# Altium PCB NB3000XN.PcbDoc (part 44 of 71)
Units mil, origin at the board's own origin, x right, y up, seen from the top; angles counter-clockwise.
Board outline 9527.56 x 6929.77 mil, 6 copper layers (Top Layer, GND+SHIELD, MidLayer1, MidLayer2, P2 - 3V3+5V0, Bottom Layer), stack 62.375 mil thick; 832 components, 1027 nets, 4655 pads, 4981 vias.
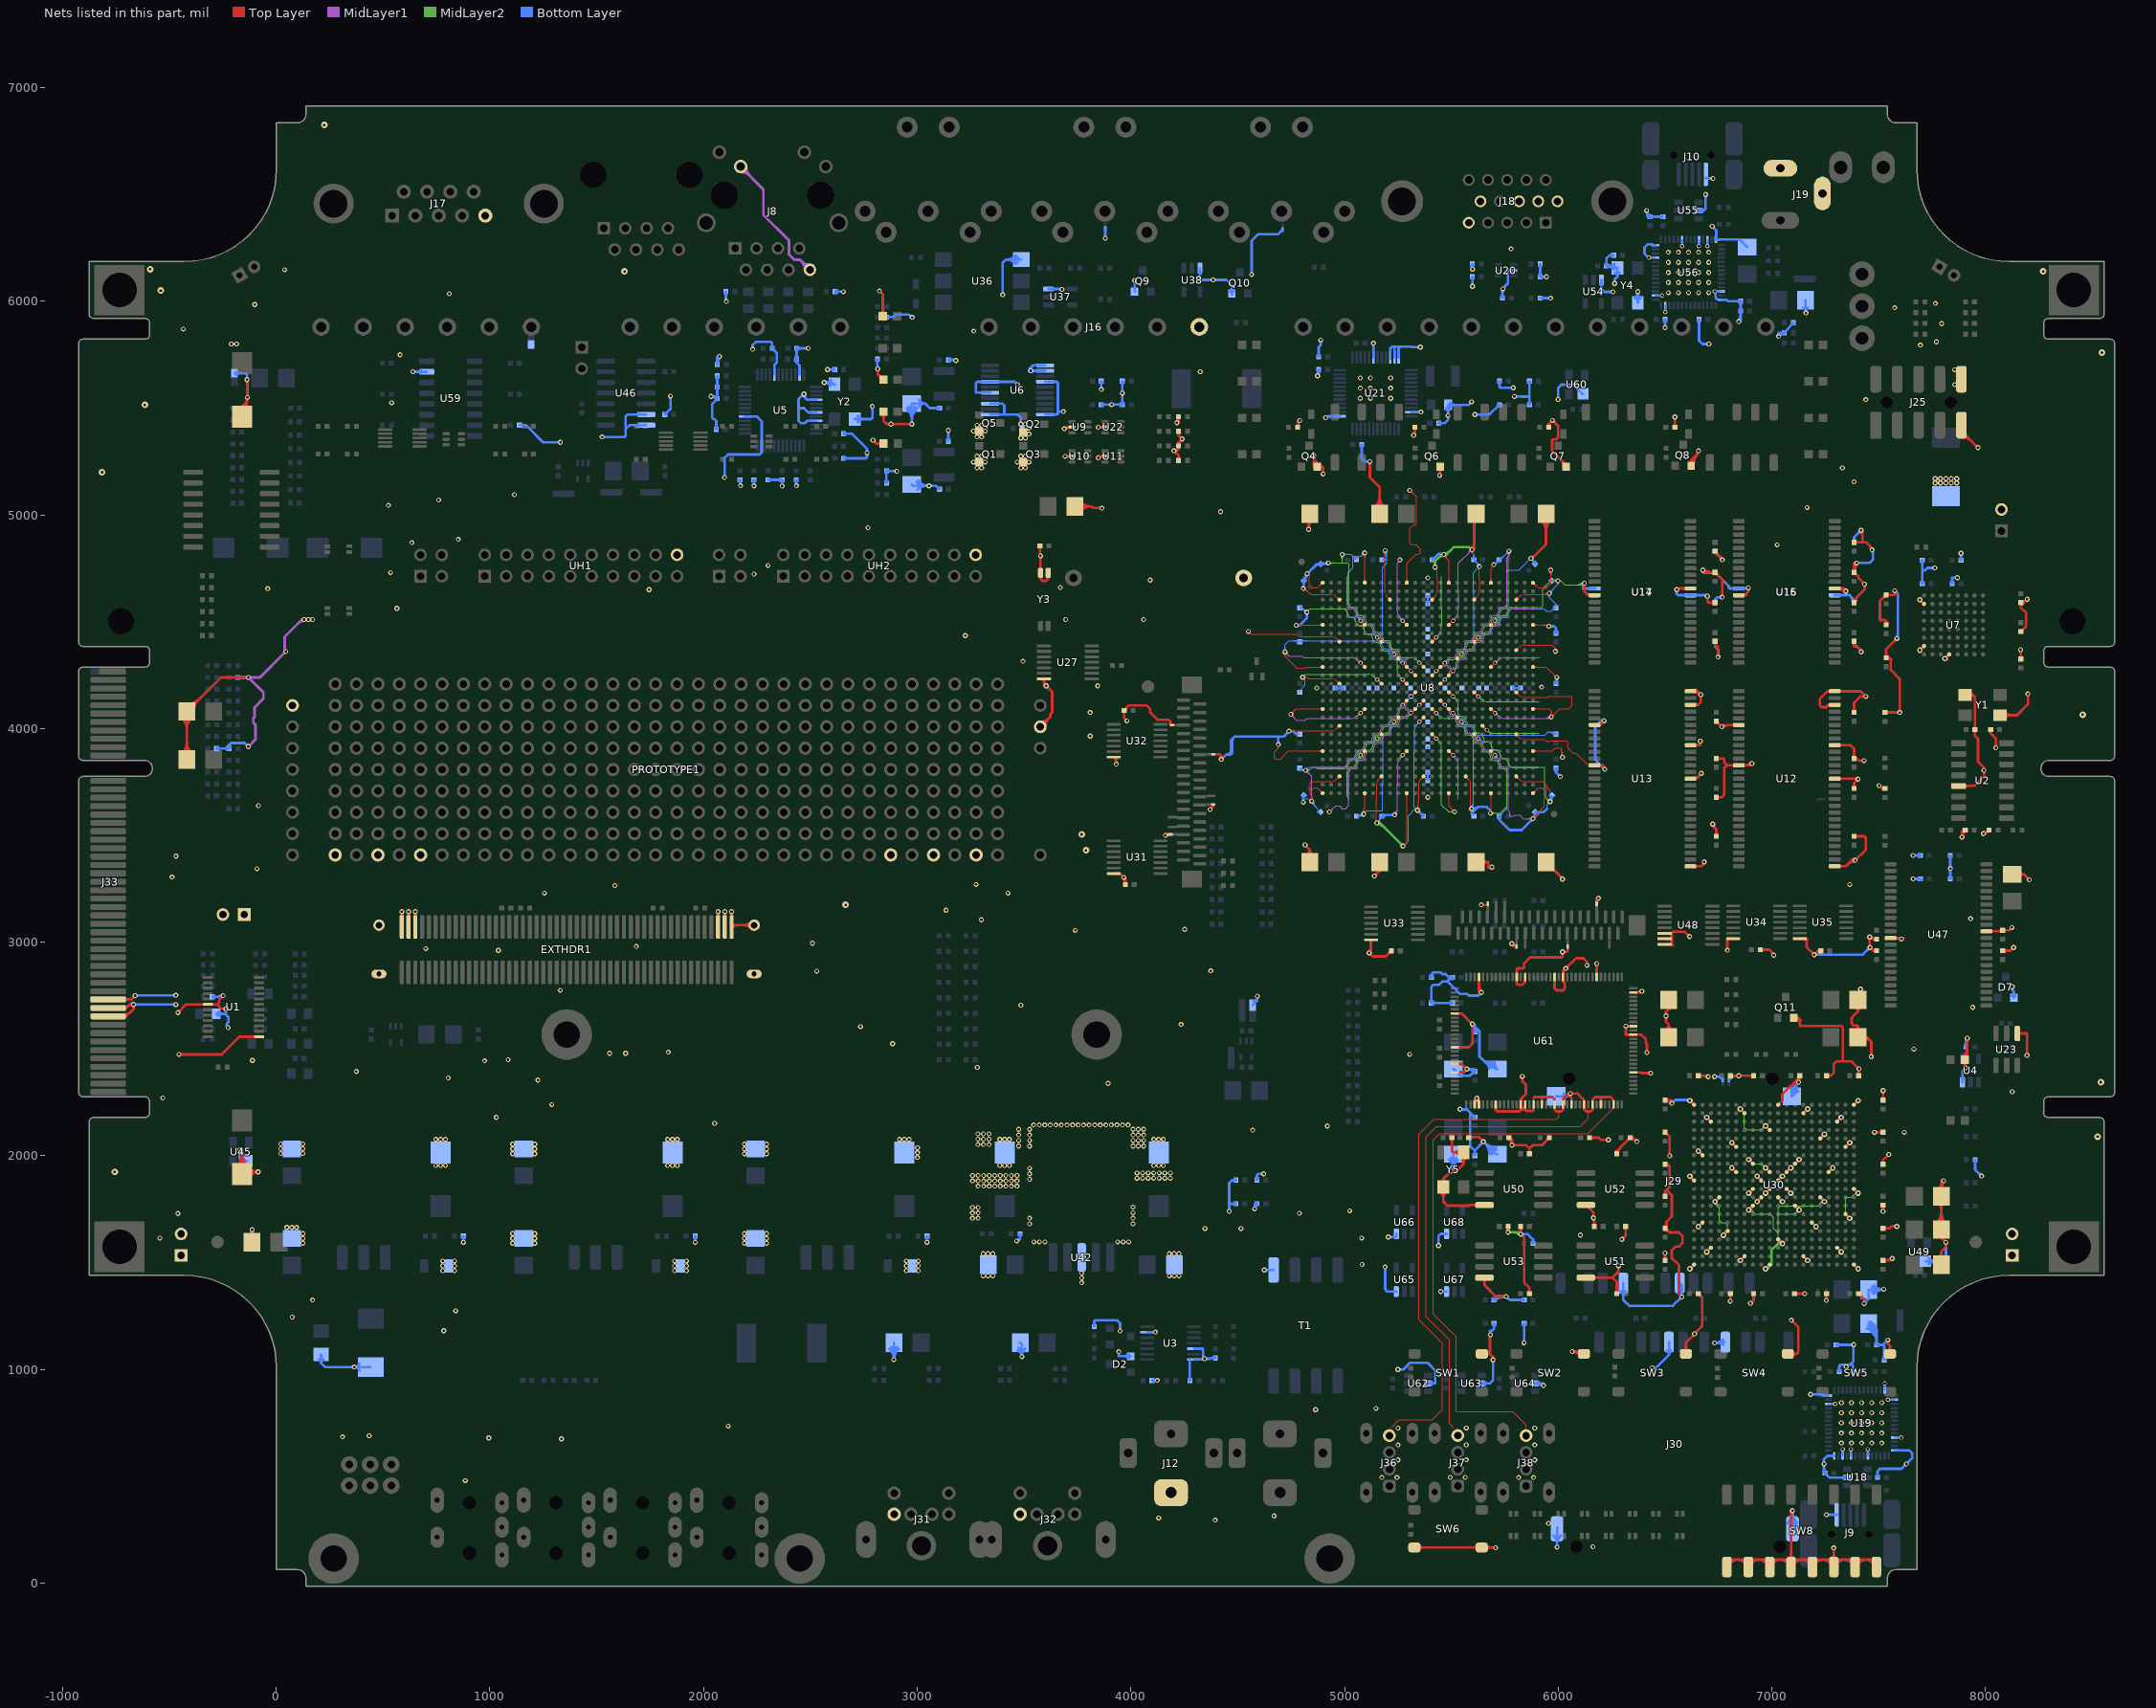
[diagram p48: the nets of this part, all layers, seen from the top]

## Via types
v1: diameter 23, hole 11.81, Top Layer to Bottom Layer, 3672 vias
v2: diameter 26, hole 11.81, Top Layer to Bottom Layer, 461 vias
v3: diameter 19, hole 11.81, Top Layer to Bottom Layer, tented both sides, 396 vias
v4: diameter 23.62, hole 11.81, Top Layer to Bottom Layer, 288 vias
v5: diameter 20, hole 11.81, Top Layer to Bottom Layer, 91 vias
v6: diameter 23, hole 11.81, Top Layer to Bottom Layer, tented both sides, 50 vias
v7: diameter 31, hole 11.81, Top Layer to Bottom Layer, 15 vias
v8: diameter 27.56, hole 11.81, Top Layer to Bottom Layer, tented both sides, 4 vias
v9: diameter 29, hole 11.81, Top Layer to Bottom Layer, 3 vias
v10: diameter 21, hole 11.81, Top Layer to Bottom Layer, 1 vias

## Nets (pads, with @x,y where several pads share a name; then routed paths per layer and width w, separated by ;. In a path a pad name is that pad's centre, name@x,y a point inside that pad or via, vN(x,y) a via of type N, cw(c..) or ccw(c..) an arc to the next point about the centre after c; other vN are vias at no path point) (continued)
GND: (continued)
  Bottom Layer w4: v1@4714.47,4365.09 ccw(c4698.26,4381.31) 4721.19,4381.31 ccw(c4744.13,4381.31) v1@4727.91,4365.09 ; v1@4717.3,4362.26 ccw(c4707.91,4371.65) 4721.19,4371.65 ccw(c4734.47,4371.65) v1@4725.08,4362.26 ; v1(4721.19,4358.37) 4721.19,4391.95 4739.86,4410.62 C320.2@4790,4410.62 ; 4754.08,4410.62 cw(c4754.08,4369.63) C320.2@4783.06,4398.61 ; 4763.73,4410.62 cw(c4763.73,4379.28) C320.2@4785.89,4401.44 ; 4765.19,3982.78 4765.19,3983.04 ; 4773.39,4410.62 cw(c4773.39,4388.94) C320.2@4788.72,4404.27 ; C320.2@4778.55,4410.62 ccw(c4778.55,4417) C320.2@4783.06,4412.49 ; C323.2@4781.37,3969.77 ccw(c4773.52,3965.52) 4773.52,3974.45 ; C323.2@4781.37,3979.12 cw(c4773.52,3983.38) 4773.52,3974.45 ; C322.2@4787.93,3814.28 ccw(c4800.95,3818.83) C322.2@4800.95,3805.04 ; C322.2@4790,3815 C322.2@4799.96,3805.04 ; C323.2@4790,3974.45 4773.52,3974.45 ; C335.2@4790,4169.33 4790,4178.56 4815.19,4203.75 4815.19,4229.04 v1(4803.86,4240.37) ; C320.2@4790,4405.55 4795.07,4410.62 4860,4410.62 4870,4410.62 4938.04,4410.62 5153.78,4410.62 cw(c5153.78,4386.85) 5177.55,4386.85 ccw(c5193.15,4386.85) 5193.15,4371.25 cw(c5193.15,4347.48) 5216.92,4347.48 ; C304.2@4790,4559.19 cw(c4790,4513.22) v1@4822.51,4545.72 ; C304.2@4790,4563.19 cw(c4790,4526.87) v1@4815.68,4552.55 ; C304.2@4790,4565 4803.23,4565 v1(4823.52,4544.71) 4838.75,4559.93 4855.26,4559.93 4860,4559.93 4870,4559.93 4879.78,4559.93 4938.04,4559.93 4996.3,4559.93 cw(c4996.3,4544.33) 5011.9,4544.33 ccw(c5035.67,4544.33) 5035.67,4520.56 cw(c5035.67,4504.96) 5051.27,4504.96 ccw(c5075.04,4504.96) 5075.04,4481.19 cw(c5075.04,4465.59) 5090.64,4465.59 ccw(c5114.41,4465.59) 5114.41,4441.82 5122.53,4441.82 ; C304.2@4790,4567.19 cw(c4790,4540.53) 4808.85,4559.38 ; C304.2@4790,4571.19 cw(c4790,4554.19) 4802.02,4566.21 ; C320.2@4791.28,4404.27 cw(c4806.61,4388.94) 4806.61,4410.62 ; C322.2@4791.71,3815.6 ccw(c4806.58,3820.8) v1@4806.58,3805.04 ; C320.2@4794.11,4401.44 cw(c4816.27,4379.28) 4816.27,4410.62 ; C322.2@4795.49,3816.92 ccw(c4812.22,3822.77) v1@4812.22,3805.04 ; C320.2@4796.94,4398.61 cw(c4825.92,4369.63) 4825.92,4410.62 ; C320.2@4796.94,4412.49 ccw(c4801.45,4417) C320.2@4801.45,4410.62 ; C322.2@4799.26,3818.24 ccw(c4817.86,3824.74) v1(4817.86,3805.04) ; v1@4800.28,4661.72 ccw(c4777.82,4684.18) C310.2@4809.59,4684.18 ; C310.2@4802.65,4684.73 cw(c4785.9,4667.98) 4809.59,4667.98 cw(c4833.27,4667.99) C310.2@4816.53,4684.73 ; v1@4803.11,4658.89 ccw(c4787.47,4674.53) 4809.59,4674.53 ; C310.2@4805.48,4687.56 cw(c4795.56,4677.64) 4809.59,4677.64 cw(c4823.62,4677.64) C310.2@4813.7,4687.56 ; C327.2@4809.59,3688.33 4809.59,3672.04 4834.19,3672.04 v1(4846.19,3660.04) 4846.19,3651.71 4875.19,3622.71 4875.19,3609.59 C326.2@4888.33,3609.59 ; v1@4809.59,4659.98 C310.2@4809.59,4691.67 ; 4809.59,4671.69 ccw(c4823.69,4671.69) v1@4813.72,4661.72 ; v1@4809.99,3799.72 ccw(c4799.96,3792.93) C322.2@4799.96,3805.04 ; v1@4809.99,3810.36 cw(c4799.96,3817.15) C322.2@4799.96,3805.04 ; v1@4814.02,4544.71 ccw(c4791.09,4544.71) 4807.31,4560.93 ccw(c4823.52,4577.14) v1@4823.52,4554.21 ; v1@4817.52,4717.37 v1(4825.19,4725.04) ; v1@4817.86,3813.37 v1(4817.86,3805.04) ; v1@4818.02,4544.71 ccw(c4804.75,4544.71) 4814.14,4554.1 ccw(c4823.52,4563.49) v1@4823.52,4550.21 ; v1@4825.92,3800.02 cw(c4834.97,3794.38) 4834.97,3805.04 ; v1@4825.92,3810.07 ccw(c4834.97,3815.71) 4834.97,3805.04 ; v1@4847.69,3660.04 ccw(c4871.43,3660.04) 4854.64,3643.25 ; v1@4851.69,3660.04 ccw(c4885.09,3660.04) 4861.47,3636.43 ; v1@4855.69,3660.04 ccw(c4898.74,3660.04) 4868.3,3629.6 ; v1(4988.86,4815.04) 5031.3,4815.04 5040.19,4806.15 ; v1@4992.75,4811.15 cw(c5002.14,4801.76) 5002.14,4815.04 cw(c5002.14,4828.32) v1@4992.75,4818.93 ; v1@4995.57,4808.32 cw(c5011.79,4792.11) 5011.79,4815.04 cw(c5011.79,4837.98) v1@4995.57,4821.76 ; 5020.07,3670 5020.07,3679.78 5020.07,3738.04 5020.07,3796.3 cw(c5035.67,3796.3) 5035.67,3811.9 ccw(c5035.67,3835.67) 5059.44,3835.67 5059.44,3843.79 ; 5020.07,4700.22 5020.07,4670 ; 5020.07,4724.74 5020.07,4732.25 ; C308.2@5046.53,4790.26 ccw(c5024.87,4790.82) 5040.19,4806.15 ; C308.2@5050.53,4790.15 ccw(c5037.7,4790.49) 5046.77,4799.56 ccw(c5055.85,4808.64) C308.2@5056.19,4795.81 ; C308.2@5056.08,4799.81 cw(c5055.51,4821.47) 5040.19,4806.15 ; C308.2@5056.34,4790 5040.19,4806.15 ; 5059.44,4536.21 5059.44,4544.33 ccw(c5035.67,4544.33) 5035.67,4568.1 cw(c5035.67,4583.7) 5020.07,4583.7 5020.07,4641.96 5020.07,4670 ; 5059.49,3843.84 cw(c5083.21,3845.45) 5064.61,3860.24 ; 5059.49,4536.16 ccw(c5083.21,4534.55) 5064.61,4519.76 ; C331.2@5060.45,3585.89 cw(c5070.37,3575.97) 5070.37,3590 cw(c5070.37,3604.03) C331.2@5060.45,3594.11 ; C331.2@5063.28,3583.06 cw(c5080.02,3566.32) 5080.02,3590 cw(c5080.03,3613.69) C331.2@5063.28,3596.94 ; C331.2@5063.27,3590 ccw(c5063.27,3615.59) v1@5085.43,3602.79 ; v3@5067.65,3873.74 cw(c5049.82,3870.59) 5064.65,3860.21 cw(c5079.49,3849.82) v3@5076.34,3867.65 ; v3@5067.65,4506.26 ccw(c5049.82,4509.41) 5064.65,4519.79 ccw(c5079.49,4530.18) v3@5076.34,4512.35 ; 5070.2,3590 ccw(c5070.2,3611.59) v1@5088.89,3600.79 ; 5077.13,3590 ccw(c5077.13,3607.58) v1@5092.36,3598.79 ; v1@5081.96,3604.79 cw(c5056.34,3619.59) C331.2@5056.34,3590 5088.48,3590 5090.19,3591.71 v1(5090.19,3600.04) 5105.15,3615 5175,3615 5177.55,3617.55 5177.55,3655.26 5177.55,3660 5177.55,3670 5177.55,3679.78 5177.55,3738.04 5177.55,3953.78 cw(c5193.15,3953.78) 5193.15,3969.38 ccw(c5193.15,3993.15) 5216.92,3993.15 5216.92,4001.27 ; 5084.06,3590 ccw(c5084.06,3603.58) v1@5095.82,3596.79 ; v1@5085.02,4822.37 cw(c5062.09,4822.37) 5078.31,4806.16 cw(c5094.52,4789.94) v1@5094.52,4812.87 ; v1@5089.02,4822.37 cw(c5075.75,4822.37) 5085.14,4812.99 cw(c5094.52,4803.6) v1@5094.52,4816.87 ; v1(5094.52,4822.37) 5078.3,4806.15 5040.19,4806.15 ; 5122.53,3938.18 5114.41,3938.18 ccw(c5114.41,3914.41) 5090.64,3914.41 cw(c5075.04,3914.41) 5075.04,3898.81 ccw(c5075.04,3875.04) 5051.27,3875.04 cw(c5035.67,3875.04) 5035.67,3859.44 ccw(c5035.67,3835.67) 5011.9,3835.67 cw(c4996.3,3835.67) 4996.3,3820.07 4938.04,3820.07 4879.78,3820.07 4870,3820.07 4860,3820.07 4855.26,3820.07 4850,3820.07 4834.97,3805.04 ; 5122.58,3938.23 ccw(c5124.19,3961.95) 5138.98,3943.35 ; 5122.58,4441.77 cw(c5124.19,4418.05) 5138.98,4436.65 ; v3@5146.39,3955.08 cw(c5128.56,3958.23) 5138.95,3943.39 cw(c5149.33,3928.56) v3@5152.48,3946.39 ; v3@5146.39,4424.92 ccw(c5128.56,4421.77) 5138.95,4436.61 ccw(c5149.33,4451.44) v3@5152.48,4433.61 ; v1(5150.86,3558.37) 5178.47,3585.98 5181.86,3589.37 5181.86,3590 C330.2@5174.45,3590 ; v1@5150.86,3563.87 ccw(c5150.86,3577.15) 5160.25,3567.76 ccw(c5169.64,3558.37) v1@5156.36,3558.37 ; v1@5150.86,3567.87 ccw(c5150.86,3590.81) 5167.07,3574.59 ; C298.2@5151.81,4190 C298.2@5153.78,4191.97 ; v1@5154.88,3562.39 ccw(c5130.94,3586.33) C330.2@5164.67,3589.18 ; v1@5160.36,3558.37 cw(c5183.29,3558.37) 5167.07,3574.59 ; 5160.97,3568.48 ccw(c5142.17,3587.28) C330.2@5168.66,3589.51 ; C330.2@5172.64,3589.85 cw(c5153.41,3588.23) 5167.06,3574.57 ; C292.2@5174.45,4790 5198.52,4790 ; C292.2@5178.56,4785.89 cw(c5188.48,4775.97) 5188.48,4790 cw(c5188.48,4804.03) C292.2@5178.56,4794.11 ; C292.2@5181.39,4783.06 cw(c5198.13,4766.31) 5198.13,4790 cw(c5198.13,4813.69) C292.2@5181.39,4796.94 ; v1@5183.47,4826.66 cw(c5147.14,4790.32) 5198.52,4790.32 ; v1@5186.3,4829.49 cw(c5156.79,4799.98) 5198.52,4799.98 ; v1@5189.13,4832.31 cw(c5166.45,4809.63) 5198.52,4809.63 ; v1(5190.19,4833.37) 5198.52,4825.04 5198.52,4790 ; v1@5191.96,4835.14 cw(c5176.11,4819.29) 5198.52,4819.29 ; 5216.92,4378.73 5216.92,4386.85 ccw(c5193.15,4386.85) 5193.15,4410.62 cw(c5193.15,4426.22) 5177.55,4426.22 5177.55,4641.96 5177.55,4700.22 5177.55,4710 5177.55,4720 5177.55,4724.74 5177.55,4754.07 5198.52,4775.04 5198.52,4790 ; 5216.97,4001.32 cw(c5240.69,4002.93) 5222.09,4017.72 ; 5216.97,4378.68 ccw(c5240.69,4377.07) 5222.09,4362.28 ; v3@5225.13,4031.22 cw(c5207.3,4028.07) 5222.13,4017.69 cw(c5236.97,4007.3) v3@5233.82,4025.13 ; v3@5225.13,4348.78 ccw(c5207.3,4351.93) 5222.13,4362.31 ccw(c5236.97,4372.7) v3@5233.82,4354.87 ; v3@5264.5,4306.81 ccw(c5246.67,4303.66) 5257.06,4318.5 ; v3@5270.59,4315.5 cw(c5267.44,4333.33) 5257.06,4318.5 ; v1(5273.52,3450.04) 5298.52,3475.04 5298.52,3591.71 5333.19,3626.37 ; v1@5273.52,3455.54 ccw(c5273.52,3468.82) 5282.91,3459.43 ccw(c5292.3,3450.04) v1@5279.02,3450.04 ; v1@5273.52,3459.54 ccw(c5273.52,3482.48) 5289.74,3466.26 ccw(c5305.96,3450.04) v1@5283.02,3450.04 ; v1(5341.52,3618.04) 5326.77,3632.8 5326.77,3655.26 5326.77,3660 5326.77,3670 5326.77,3876.1 5326.77,3895.52 5326.77,3969.64 5326.77,3989.14 cw(c5368.5,3989.14) 5338.99,4018.65 ; v3@5343.16,4031.87 cw(c5325.12,4030.29) 5338.99,4018.65 ; v3@5351.28,4025.05 ccw(c5352.86,4007.01) 5338.99,4018.65 ; C333.2@5365.19,3590 C333.2@5365.19,3594.37 ; v3@5509.41,4064.5 cw(c5512.56,4046.67) 5522.94,4061.5 ; v3@5515.5,4073.19 ccw(c5533.33,4076.34) 5522.94,4061.5 ; v3@5546.18,4025.13 cw(c5543.03,4007.3) 5557.87,4017.69 cw(c5572.7,4028.07) v3@5554.87,4031.22 ; v3@5546.18,4354.87 ccw(c5543.03,4372.7) 5557.87,4362.31 ccw(c5572.7,4351.93) v3@5554.87,4348.78 ; 5557.91,4017.72 cw(c5539.31,4002.93) 5563.03,4001.32 ; 5557.91,4362.28 ccw(c5539.31,4377.07) 5563.03,4378.68 ; 5563.08,4001.27 5563.08,3993.15 ccw(c5586.85,3993.15) 5586.85,3969.38 cw(c5586.85,3953.78) 5602.45,3953.78 5602.45,3738.04 5602.45,3679.78 5602.45,3670 5602.45,3660 5602.45,3655.26 ; 5563.08,4378.73 5563.08,4386.85 cw(c5586.85,4386.85) 5586.85,4410.62 ccw(c5586.85,4426.22) 5602.45,4426.22 5602.45,4641.96 5602.45,4700.22 5602.45,4710 5602.45,4720 5602.45,4728.97 5610.52,4737.04 v1(5631.86,4758.37) 5631.86,4763.69 C291.2@5605.55,4790 5605.55,4814.04 v1@5593.55,4826.04 ; v1@5589.49,3632.96 ccw(c5576.8,3655.26) 5602.45,3655.26 ; v1@5591.47,3629.49 ccw(c5580.71,3648.38) 5602.45,3648.38 ; v1@5593.45,3626.01 ccw(c5584.63,3641.5) 5602.45,3641.5 ; v1@5593.52,4826.04 5596.19,4828.71 v1(5596.19,4837.04) ; 5594.19,3603.07 5605.55,3591.71 C328.2@5605.55,3590 ; v1(5594.19,3624.71) v1@5602.45,3624.71 ; v1@5595.43,3622.54 ccw(c5588.55,3634.62) 5602.45,3634.62 ; C291.2@5598.61,4796.94 ccw(c5581.86,4813.69) 5605.55,4813.69 ccw(c5629.24,4813.68) C291.2@5612.49,4796.94 ; C291.2@5601.44,4794.11 ccw(c5591.52,4804.03) 5605.55,4804.03 ccw(c5619.58,4804.03) C291.2@5609.66,4794.11 ; C291.2@5605.55,4780.19 cw(c5605.55,4756.5) 5622.3,4773.25 cw(c5639.05,4790) C291.2@5615.36,4790 ; C291.2@5605.55,4784.19 cw(c5605.55,4770.16) 5615.47,4780.08 cw(c5625.39,4790) C291.2@5611.36,4790 ; 5606.86,3616.04 5606.86,3617.37 5602.45,3621.78 v1@5602.45,3624.71 ; C291.2@5611.88,4783.67 cw(c5586.58,4758.38) v1@5622.36,4758.38 ; 5618.71,4776.84 cw(c5600.24,4758.38) v1@5626.36,4758.37 ; 5624.72,4770.83 ccw(c5631.86,4777.97) v1@5631.86,4767.87 ; 5625.54,4770.02 cw(c5613.89,4758.38) v1@5630.36,4758.37 ; C296.2@5626.22,4188.03 C296.2@5628.19,4190 ; v3@5627.52,3946.39 cw(c5630.67,3928.56) 5641.05,3943.39 cw(c5651.44,3958.23) v3@5633.61,3955.08 ; v3@5627.52,4433.61 ccw(c5630.67,4451.44) 5641.05,4436.61 ccw(c5651.44,4421.77) v3@5633.61,4424.92 ; 5641.02,3943.35 ccw(c5655.81,3961.95) 5657.42,3938.23 ; 5641.02,4436.65 cw(c5655.81,4418.05) 5657.42,4441.77 ; 5657.47,3938.18 5665.59,3938.18 cw(c5665.59,3914.41) 5689.36,3914.41 ccw(c5704.96,3914.41) 5704.96,3898.81 cw(c5704.96,3875.04) 5728.73,3875.04 ccw(c5744.33,3875.04) 5744.33,3859.44 cw(c5744.33,3835.67) 5768.1,3835.67 ccw(c5783.7,3835.67) 5783.7,3820.07 5841.96,3820.07 5900.22,3820.07 5910,3820.07 ; 5657.47,4441.82 5665.59,4441.82 ccw(c5665.59,4465.59) 5689.36,4465.59 cw(c5704.96,4465.59) 5704.96,4481.19 ccw(c5704.96,4504.96) 5728.73,4504.96 cw(c5744.33,4504.96) 5744.33,4520.56 ccw(c5744.33,4544.33) 5768.1,4544.33 cw(c5783.7,4544.33) 5783.7,4559.93 5841.96,4559.93 5910,4559.93 5920,4559.93 5935.11,4559.93 5945,4550.04 5966.83,4550.04 ; C312.2@5665.59,4190 C312.2@5674.82,4190 ; v1(5698.52,4767.37) 5701.19,4767.37 5706.19,4772.37 5706.19,4772.53 5710.04,4776.37 ; v3@5703.66,3867.65 cw(c5700.51,3849.82) 5715.35,3860.21 cw(c5730.18,3870.59) v3@5712.35,3873.74 ; v3@5703.66,4512.35 ccw(c5700.51,4530.18) 5715.35,4519.79 ccw(c5730.18,4509.41) v3@5712.35,4506.26 ; C307.2@5713.97,4788.47 cw(c5700.13,4786.28) 5710.04,4776.38 ; 5715.39,3860.24 cw(c5696.79,3845.45) 5720.51,3843.84 ; 5715.39,4519.76 ccw(c5696.79,4534.55) 5720.51,4536.16 ; C307.2@5717.77,4778.95 cw(c5721.24,4775.48) C307.2@5722.05,4780.32 ; 5720.56,3843.79 5720.56,3835.67 ccw(c5744.33,3835.67) 5744.33,3811.9 cw(c5744.33,3796.3) 5759.93,3796.3 5759.93,3738.04 5759.93,3695 ; 5720.56,4536.21 5720.56,4544.33 cw(c5744.33,4544.33) 5744.33,4568.1 ccw(c5744.33,4583.7) 5759.93,4583.7 5759.93,4641.96 5759.93,4700.22 5759.93,4710 5759.93,4720 5759.93,4724.74 5759.93,4733.37 5768.26,4741.71 5816.86,4741.71 v1(5872.19,4797.04) ; C307.2@5722.13,4780.31 ccw(c5719.95,4766.47) 5710.04,4776.38 ; C329.2@5723.66,3590 C329.2@5731.86,3598.2 ; C329.2@5723.66,3595.81 ccw(c5723.66,3609.84) 5733.58,3599.92 ccw(c5743.5,3590) C329.2@5729.47,3590 ; C329.2@5723.66,3599.81 ccw(c5723.66,3623.5) 5740.41,3606.75 ccw(c5757.16,3590) C329.2@5733.47,3590 ; C307.2@5723.66,4790 5710.04,4776.37 ; C307.2@5723.66,4791.81 ccw(c5723.66,4808.62) 5735.55,4796.74 ; C307.2@5723.66,4795.81 ccw(c5723.66,4822.28) 5742.38,4803.56 ; C307.2@5723.66,4799.81 ccw(c5723.66,4835.94) 5749.21,4810.39 ; C329.2@5731.86,3590 C329.2@5731.86,3598.2 ; C307.2@5733.47,4790 cw(c5744.72,4790) 5736.77,4797.95 ; v1@5760.36,4831.04 cw(c5737.42,4831.04) 5753.64,4814.82 cw(c5769.86,4798.61) v1@5769.86,4821.54 ; v1@5764.36,4831.04 cw(c5751.08,4831.04) 5760.47,4821.65 cw(c5769.86,4812.26) v1@5769.86,4825.54 ; v1(5769.86,4831.04) 5726.24,4787.42 5715.19,4776.37 5710.04,4776.37 ; v1@5878.02,3586.74 ccw(c5865.73,3609.59) C324.2@5891.67,3609.59 5891.67,3587.52 ; v1@5879.92,3583.22 ccw(c5869.33,3602.89) C324.2@5891.67,3602.89 ; v1@5881.81,3579.7 ccw(c5872.93,3596.2) C324.2@5891.67,3596.2 ; v1(5882.52,3578.37) 5891.67,3587.52 ; v1@5883.71,3576.17 ccw(c5876.54,3589.5) 5891.67,3589.5 ; C324.2@5885.1,3602.3 cw(c5871.77,3587.52) 5891.67,3587.52 ; C324.2@5887.78,3605.27 cw(c5879.88,3596.52) 5891.67,3596.52 cw(c5903.46,3596.52) C324.2@5895.56,3605.27 ; C324.2@5898.24,3602.3 ccw(c5911.58,3587.52) 5891.67,3587.52 ; 5948.52,3625.04 5948.52,3645.37 v1(5961.52,3658.37) 5970.41,3667.26 ; v1@5951.97,4625.92 cw(c5942.4,4613.78) 5957.86,4613.78 ; v1@5957.23,3666.85 ccw(c5946.33,3688.33) C325.2@5970.41,3688.33 5970.41,3667.26 ; v1@5957.86,4638.87 ccw(c5957.86,4652.15) 5967.25,4642.76 ccw(c5976.64,4633.37) v1@5963.36,4633.37 ; v1@5957.86,4642.87 ccw(c5957.86,4665.81) 5974.07,4649.59 ccw(c5990.29,4633.37) v1@5967.36,4633.37 ; v1@5959.04,3663.28 ccw(c5949.63,3681.81) C325.2@5970.41,3681.81 ; 5959.48,3983.37 cw(c5959.48,3950.21) C305.2@5985.45,3970.83 ; v1@5960.85,3659.71 ccw(c5952.94,3675.3) C325.2@5970.41,3675.3 ; v1@5962.66,3656.15 ccw(c5956.24,3668.78) 5970.41,3668.78 ; v1@5963.74,4625.92 ccw(c5973.32,4613.78) 5957.86,4613.78 ; C325.2@5964.1,3680.82 cw(c5952.71,3667.26) 5970.41,3667.26 ; C325.2@5966.67,3683.88 cw(c5959.93,3675.85) 5970.41,3675.85 cw(c5980.9,3675.85) C325.2@5974.15,3683.88 ; 5967.45,4550.66 5966.9,4550.11 ; 5967.76,3983.37 cw(c5967.76,3956.79) C305.2@5988.58,3973.32 ; 5970.27,4553.27 cw(c5985.48,4538.05) C303.2@5989.04,4559.27 ; C309.2@5970.41,4691.67 v1(5998.52,4691.71) v1(5998.52,4691.71) 5998.52,4674.04 ; C309.2@5974.52,4687.56 cw(c5984.44,4677.64) 5984.44,4691.67 cw(c5984.44,4705.7) C309.2@5974.52,4695.78 ; C309.2@5975.5,4691.67 ccw(c5975.5,4714.73) v1@5991.81,4698.43 ; C309.2@5975.68,4691.67 cw(c5975.68,4668.86) v1@5991.81,4684.99 ; 5975.75,4558.75 cw(c5987.05,4547.45) C303.2@5989.7,4563.21 ; 5976.05,3983.37 cw(c5976.05,3963.37) C305.2@5991.71,3975.81 ; C325.2@5976.73,3680.82 ccw(c5988.12,3667.27) 5970.41,3667.27 ; C309.2@5977.35,4684.73 cw(c5994.1,4667.99) v1@5994.1,4691.67 ; C309.2@5977.35,4698.61 ccw(c5994.1,4715.36) v1@5994.1,4691.67 ; C305.2@5982.32,3968.35 ccw(c5951.19,3943.63) 5951.19,3983.37 ; C309.2@5985.16,4691.67 ccw(c5985.16,4705.07) v1@5994.64,4695.6 ; C303.2@5985.25,4573.59 ccw(c5980.8,4581.64) 5990,4581.64 ; C309.2@5985.33,4691.67 cw(c5985.33,4678.52) v1@5994.64,4687.82 ; C303.2@5990,4565 5990,4581.64 ; C305.2@5990.19,3974.71 5981.52,3983.37 5951.19,3983.37 ; v1@5993.29,4683.78 cw(c5986.85,4674.04) 5998.52,4674.04 ; C303.2@5994.75,4573.59 cw(c5999.2,4581.64) 5990,4581.64 ; v1@6003.76,4683.78 ccw(c6010.2,4674.04) 5998.52,4674.04 ; 6115.19,4655.37 cw(c6133.18,4655.37) v1@6126.21,4671.95 ; 6115.19,4661.39 cw(c6130.65,4661.39) v1@6124.66,4675.64 ; 6115.19,4667.41 cw(c6128.12,4667.41) v1@6123.11,4679.33 ; 6115.9,4655.75 6115.19,4656.45 6115.19,4673.37 v1(6122.52,4680.71) ; 6131.86,4655.75 6170,4655.75 U14.34@6170.59,4655.75 ; U14.34@6147.37,4650.09 ccw(c6133.72,4636.43) 6133.72,4655.75 ccw(c6133.72,4675.06) U14.34@6147.37,4661.4 ; C322.2@4799.96,3805.04 v1(4817.86,3805.04) ; v1(4817.86,3805.04) 4834.97,3805.04 ; 5020.07,4670 5020.07,4710 5020.07,4720 5020.07,4732.25 ; 5020.07,4732.25 5020.07,4732.37 5020.19,4732.37 ; 5020.07,4732.25 5020.19,4732.37 ; 5020.19,4732.37 5040.19,4752.37 5040.19,4806.15 ; 5216.92,4347.48 ccw(c5232.52,4347.48) 5232.52,4331.88 ; 5216.92,4347.48 ccw(c5232.52,4347.48) 5232.52,4331.88 ; 5232.52,4331.88 cw(c5232.52,4308.11) 5249.33,4324.92 5257.06,4318.5 ; 5522.94,4061.5 5530.67,4055.08 ccw(c5547.48,4071.89) 5547.48,4048.12 ; 5547.48,4048.12 cw(c5547.48,4032.52) 5563.08,4032.52 ; 5547.48,4048.12 cw(c5547.48,4032.52) 5563.08,4032.52 ; 5563.08,4032.52 ccw(c5586.85,4032.52) 5586.85,4008.75 cw(c5586.85,3993.15) 5602.45,3993.15 ccw(c5626.22,3993.15) 5626.22,3969.38 5841.96,3969.38 5910,3969.38 5920,3969.38 5937.19,3969.38 5951.19,3983.37 ; v1@5602.45,3624.71 v1@5602.45,3624.78 ; v1@5602.45,3624.71 5602.52,3624.71 v1@5602.45,3624.78 ; v1@5602.45,3624.78 5602.45,3655.26 ; C329.2@5731.86,3598.2 5759.93,3626.27 5759.93,3660 5759.93,3670 ; 5759.93,3670 5759.93,3679.78 5759.93,3695 ; 5759.93,3670 5759.93,3695 ; 5957.86,4613.78 5990,4581.64 ; 5957.86,4613.78 v1(5957.86,4633.37) 5998.52,4674.04 ; 5966.83,4550.04 5966.9,4550.04 5966.9,4550.11 ; 5966.83,4550.04 5966.9,4550.11 ; 5966.9,4550.11 5968.57,4551.78 5968.78,4551.78 5976.78,4559.78 5976.78,4568.41 5990,4581.64
  Bottom Layer w5: C274.2@5388.03,4032.52 C274.2@5390,4030.55 ; C270.2@5388.03,4111.26 C270.2@5390,4109.29 ; v3(5508.11,4150.63) v3@5510.08,4150.63
  Bottom Layer w8: v3@5269.92,4229.37 v3(5271.89,4229.37) ; v3@5309.29,4152.6 v3(5311.26,4150.63) ; C317.2@5384.48,3762.45 ccw(c5371.14,3775.79) 5390,3775.79 ccw(c5408.86,3775.79) C317.2@5395.52,3762.45 ; C301.2@5384.48,3788.81 cw(c5371.14,3775.47) 5390,3775.47 cw(c5408.86,3775.47) C301.2@5395.52,3788.81 ; C299.2@5384.48,4591.19 ccw(c5371.14,4604.53) 5390,4604.53 ccw(c5408.86,4604.53) C299.2@5395.52,4591.19 ; C315.2@5384.48,4617.55 cw(c5371.14,4604.21) 5390,4604.21 cw(c5408.86,4604.21) C315.2@5395.52,4617.55 ; C317.2@5390,3756.93 C301.2@5390,3794.33 C301.2@5390,3800.73 ; C313.2@5390,3908.01 C313.2@5390,3914.41 ; C272.2@5390,4347.48 C272.2@5390,4349.45 ; C299.2@5390,4579.27 C299.2@5390,4585.67 C315.2@5390,4623.07 ; v3@5427.4,3951.81 v3(5429.37,3953.78) ; v3@5427.4,4270.71 v3(5429.37,4268.74) ; v3@5427.4,4428.19 v3(5429.37,4426.22) ; C300.2@5785.67,4190 C316.2@5823.07,4190 ; C300.2@5791.19,4184.48 cw(c5804.53,4171.14) 5804.53,4190 cw(c5804.53,4208.86) C300.2@5791.19,4195.52 ; C316.2@5817.55,4184.48 ccw(c5804.21,4171.14) 5804.21,4190 ccw(c5804.21,4208.86) C316.2@5817.55,4195.52 ; v5(6424.34,6203.9) U56.53@6455.67,6203.9 ; v5@6428.58,6199.66 cw(c6438.82,6189.41) 6438.82,6203.9 cw(c6438.82,6218.38) v5@6428.58,6208.14 ; U56.44@6455.67,6026.73 v5(6487,6026.73) ; v5@6482.76,6022.49 ccw(c6472.51,6012.25) 6472.51,6026.73 ccw(c6472.51,6041.22) v5@6482.76,6030.97 ; v5@6497.49,5953.58 ccw(c6487.25,5963.82) 6501.73,5963.82 ccw(c6516.22,5963.82) v5@6505.97,5953.58 ; v5(6501.73,5949.34) U56.41@6501.73,5980.67 ; v5@6576.23,6262.24 ccw(c6565.99,6272.49) 6580.47,6272.49 ccw(c6594.96,6272.49) v5@6584.72,6262.24 ; v5(6580.47,6258) U56.6@6580.47,6289.33 ; v5@6654.97,6262.24 ccw(c6644.73,6272.49) 6659.21,6272.49 ccw(c6673.7,6272.49) v5@6663.46,6262.24 ; v5(6659.21,6258) U56.10@6659.21,6289.33 ; v5@6694.34,6262.24 ccw(c6684.1,6272.49) 6698.58,6272.49 ccw(c6713.07,6272.49) v5@6702.83,6262.24 ; v5(6698.58,6258) U56.12@6698.58,6289.33 ; v5(6733,6046.42) U56.26@6764.33,6046.42 ; v5@6737.24,6042.17 cw(c6747.48,6031.93) 6747.48,6046.42 cw(c6747.48,6060.9) v5@6737.24,6050.66 ; v5@7327.17,622.76 cw(c7316.93,612.51) 7331.42,612.51 cw(c7345.9,612.51) v5@7335.66,622.76 ; U19.12@7331.42,595.67 v5(7331.42,627) ; v5@7366.54,622.76 cw(c7356.3,612.51) 7370.79,612.51 cw(c7385.27,612.51) v5@7375.03,622.76 ; U19.10@7370.79,595.67 v5(7370.79,627) ; v5@7445.28,622.76 cw(c7435.04,612.51) 7449.53,612.51 cw(c7464.01,612.51) v5@7453.77,622.76 ; U19.6@7449.53,595.67 v5(7449.53,627) ; v5@7524.03,931.42 cw(c7513.78,921.18) 7528.27,921.18 cw(c7542.75,921.18) v5@7532.51,931.42 ; U19.41@7528.27,904.33 v5@7528.27,935.37 ; v5(7543,858.27) U19.44@7574.33,858.27 ; v5@7547.24,854.03 cw(c7557.48,843.78) 7557.48,858.27 cw(c7557.49,872.75) v5@7547.24,862.51 ; U19.53@7574.33,681.1 v5(7605.66,681.1) ; v5@7601.42,676.86 ccw(c7591.18,666.62) 7591.18,681.1 ccw(c7591.18,695.59) v5@7601.42,685.34 ; U19.26@7282.52,838.58 cw(c7282.52,824.1) 7292.76,834.34 ccw(c7282.52,824.1) U19.26@7282.52,838.58 ; U19.26@7282.52,838.58 ccw(c7282.52,853.07) 7292.76,842.83 cw(c7282.52,853.07) U19.26@7282.52,838.58 ; U19.26@7265.67,838.58 v5(7297,838.58) U19.26@7265.67,838.58
  Bottom Layer w10: v3@5319.42,4150.63 ccw(c5311.26,4150.63) v3@5319.42,4150.63
  Bottom Layer w11.81: v1@6410.51,6421 cw(c6401.42,6408.8) 6416.63,6408.8 ; v1(6413.85,6425.49) v1@6416.63,6422.71 ; 6416.63,6406.14 ccw(c6433.61,6406.14) C166.2@6428.07,6390.09 ; v1@6419.02,6423.35 ccw(c6436.69,6416.03) C166.2@6423.16,6402.5 ; C166.2@6424.09,6395.67 ccw(c6409.84,6395.67) 6419.92,6405.75 ccw(c6430,6415.83) C166.2@6430,6401.57 ; v5(6424.34,6203.9) 6404.86,6223.37 6403.86,6224.37 6403.86,6252.71 6417.86,6266.71 6438.52,6266.71 6438.52,6262.95 U56.56@6455.67,6262.95 ; C166.2@6431.93,6401.25 cw(c6439.33,6422.7) v1@6416.63,6422.7 ; C166.2@6434.18,6391.49 cw(c6444.26,6381.41) 6444.26,6395.67 cw(c6444.26,6409.93) C166.2@6434.18,6399.85 ; 6435.45,6266.71 cw(c6435.45,6253.66) U56.56@6444.67,6262.89 ; C167.2@6485.82,6391.49 ccw(c6475.74,6381.41) 6475.74,6395.67 ccw(c6475.74,6409.93) C167.2@6485.82,6399.85 ; C167.2@6487.21,6398.46 C167.2@6490,6395.67 C166.2@6430,6395.67 6416.63,6409.04 v1@6416.63,6422.71 ; v1@6720.98,6345.32 cw(c6720.98,6331.81) 6730.53,6341.36 cw(c6740.09,6350.91) v1@6726.58,6350.91 ; v1(6720.98,6350.91) 6740.19,6331.71 6740.19,6300.35 6737.95,6300.35 U56.14@6737.95,6289.33 6737.95,6287.37 6751.52,6287.37 6753.48,6289.33 6848.66,6289.33 C175.2@6885,6252.99 ; U56.14@6737.89,6300.33 ccw(c6732.32,6305.89) U56.14@6740.19,6305.89 ; 6795,6000.04 6854.29,6000.04 C177.2@6854.33,6000 C176.2@6854.33,5955 6854.33,5914.33 v1(6845,5905) ; 6839.98,6000.04 cw(c6839.98,5985.64) 6850.15,5995.82 cw(c6840.07,5985.74) 6854.33,5985.74 cw(c6868.59,5985.74) C177.2@6858.51,5995.82 ; 6840.17,6000.04 ccw(c6840.17,6014.16) C177.2@6850.15,6004.18 ; v1@6841.04,5908.96 ccw(c6808.97,5941.03) 6854.33,5941.03 ; v1@6849.4,5900.6 ccw(c6837.48,5912.52) 6854.33,5912.52 ; C176.2@6850.15,5950.82 cw(c6840.07,5940.74) 6854.33,5940.74 cw(c6868.59,5940.74) C176.2@6858.51,5950.82 ; C176.2@6850.15,5959.18 ccw(c6840.07,5969.26) 6854.33,5969.26 ccw(c6868.59,5969.26) C176.2@6858.51,5959.18 ; v1@7025.47,5836.72 cw(c7044.54,5833.09) 7044.54,5852.5 ; v1@7027.62,5839.51 ccw(c7018.07,5849.06) 7031.58,5849.06 ccw(c7045.09,5849.06) v1@7035.54,5839.51 ; v1(7031.58,5835.56) 7031.58,5851.58 7032.5,5852.5 R246.2@7058.82,5852.5 ccw(c7058.82,5830.37) v1@7037.08,5834.51 ; R246.2@7054.99,5848.67 ccw(c7045.75,5839.43) 7045.75,5852.5 ccw(c7045.75,5865.57) R246.2@7054.99,5856.33 ; v1(7181.86,883.37) 7235,883.37 7240.2,878.17 U19.28@7265.45,878.17 ; v1@7185.81,879.42 cw(c7195.36,869.87) 7195.36,883.37 cw(c7195.36,896.88) v1@7185.81,887.33 ; C95.2@7300.67,1115 7381.86,1115 7381.86,1039.04 ; C95.2@7304.85,1110.82 cw(c7314.93,1100.74) 7314.93,1115 cw(c7314.93,1129.26) C95.2@7304.85,1119.18 ; 7365.89,1115 ccw(c7365.89,1134.34) v1@7379.57,1120.66 ; 7381.86,1099.18 cw(c7401.05,1099.18) v1@7387.48,1112.75 ; C89.2@7445.29,1190.82 cw(c7420.25,1125.01) C88.1@7490.67,1125.01 ; C89.2@7449.49,1201.86 cw(c7426.77,1142.14) 7490.67,1142.14 ; C89.2@7452.99,1215 7490.67,1177.32 C88.1@7490.67,1115 7520.15,1115 7521.86,1116.71 ; C89.2@7453.69,1212.9 cw(c7433.29,1159.27) 7490.67,1159.27 ; C89.2@7457.89,1223.94 cw(c7439.8,1176.4) C89.2@7490.67,1176.4 ; C88.1@7486.49,1119.18 ccw(c7476.41,1129.26) 7490.67,1129.26 ccw(c7504.93,1129.26) 7494.85,1119.18 ccw(c7504.93,1129.26) 7504.93,1115 ccw(c7504.93,1100.74) C88.1@7494.85,1110.82 ; R109.2@7522.35,1049.32 ccw(c7513.11,1058.56) 7526.18,1058.56 ccw(c7539.25,1058.56) R109.2@7530.01,1049.32 ; R109.2@7526.18,1045 7526.18,1110.68 7521.86,1115 7521.86,1116.71 ; v1@7537.93,1138.37 cw(c7524.42,1138.37) 7533.97,1128.82 cw(c7543.52,1119.27) v1@7543.52,1132.78 ; v1(7543.52,1138.37) 7521.86,1116.71 ; U19.56@7574.33,622.05 7574.93,621.45 7643.79,621.45 7656.86,608.37 ; U19.28@7265.45,878.17 U19.28@7265.67,877.95 U19.28@7265.45,878.17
